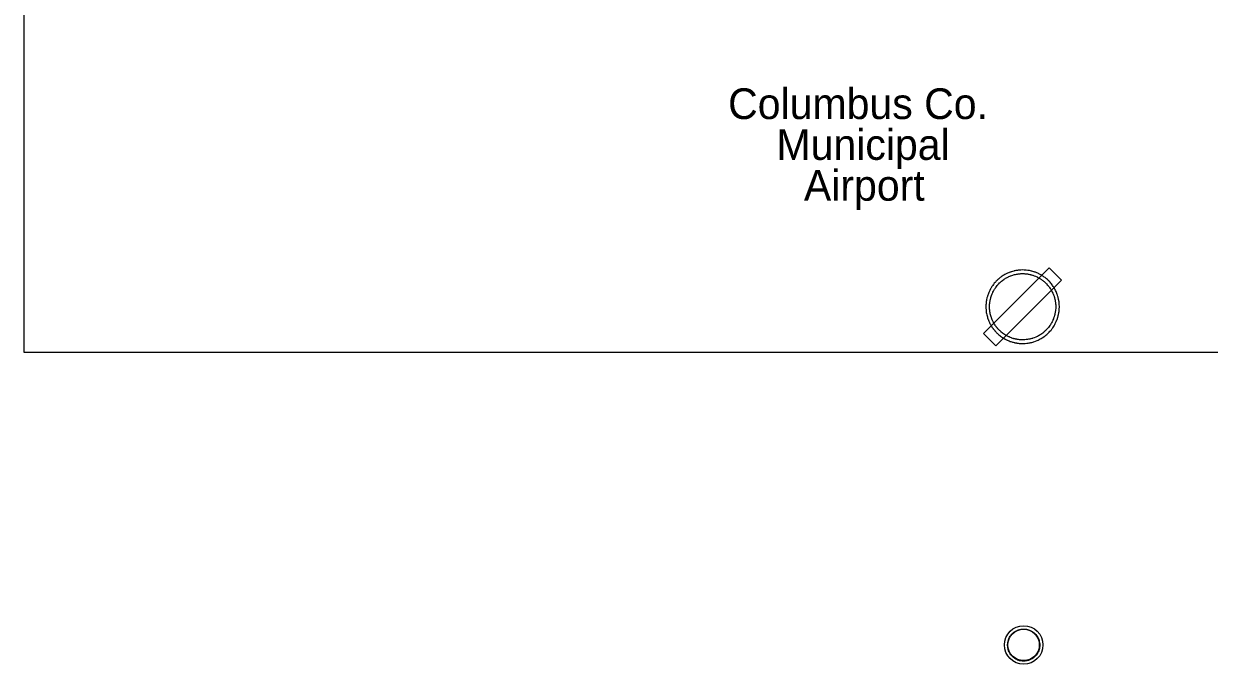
# Model space of a CAD drawing. Extents: x 5197761 to 5514561, y 1890130 to 2080942.
# Drawn here: x 5298905 to 5322096, y 1984861 to 1997380 of the extents above; entities that cross this region are included whole.
import ezdxf

# ---------------------------------------------------------------- set-up
doc = ezdxf.new("R2010")
doc.units = 0
for name, color, linetype in [('Exist Aviation Commercial or Municipal Label', 7, 'Continuous'), ('Exist Aviation Field Marked Auxiliary CELL', 7, 'Continuous'), ('Exist Civil Demographics Community CELL', 7, 'Continuous'), ('Map Preparation Inset Cut Line', 7, 'Continuous')]:
    doc.layers.add(name, color=color, linetype=linetype)

msp = doc.modelspace()

# ---------------------------------------------------------------- linework, layer by layer
at = {"layer": 'Exist Aviation Field Marked Auxiliary CELL'}
for points in [[(5319207, 1992370), (5318966, 1992611), (5317682, 1991327), (5317923, 1991086)], [(5318102, 1991216), (5318129, 1991203), (5318143, 1991196), (5318150, 1991193), (5318174, 1991183), (5318177, 1991181), (5318183, 1991179), (5318201, 1991172), (5318211, 1991169), (5318230, 1991163), (5318246, 1991158), (5318256, 1991155), (5318280, 1991149), (5318285, 1991148), (5318295, 1991146), (5318310, 1991143), (5318315, 1991142), (5318323, 1991140), (5318332, 1991139), (5318354, 1991135), (5318374, 1991133), (5318399, 1991131), (5318422, 1991130), (5318435, 1991130), (5318450, 1991130), (5318471, 1991130), (5318495, 1991131), (5318524, 1991134), (5318550, 1991137), (5318572, 1991142), (5318583, 1991143), (5318587, 1991144), (5318593, 1991146), (5318602, 1991148), (5318614, 1991150), (5318623, 1991152), (5318641, 1991157), (5318658, 1991162), (5318665, 1991165), (5318698, 1991176), (5318728, 1991188), (5318746, 1991196), (5318767, 1991206), (5318789, 1991218), (5318805, 1991226), (5318824, 1991238), (5318842, 1991250), (5318863, 1991265), (5318882, 1991279), (5318890, 1991285), (5318894, 1991288), (5318901, 1991294), (5318915, 1991305), (5318936, 1991324), (5318952, 1991340), (5318965, 1991353), (5318979, 1991368), (5318993, 1991385), (5319006, 1991400), (5319022, 1991421), (5319034, 1991438), (5319047, 1991458), (5319059, 1991477), (5319065, 1991486), (5319074, 1991503), (5319083, 1991520), (5319090, 1991533), (5319097, 1991547), (5319103, 1991562), (5319115, 1991590), (5319118, 1991600), (5319125, 1991618), (5319129, 1991631), (5319131, 1991639), (5319135, 1991650), (5319138, 1991662), (5319142, 1991679), (5319146, 1991695), (5319153, 1991731), (5319154, 1991737), (5319156, 1991756), (5319159, 1991772), (5319160, 1991784), (5319162, 1991810), (5319163, 1991841), (5319163, 1991861), (5319162, 1991888), (5319160, 1991912), (5319159, 1991923), (5319158, 1991933), (5319156, 1991945), (5319154, 1991962), (5319152, 1991970), (5319148, 1991991), (5319147, 1991997), (5319145, 1992005), (5319142, 1992019), (5319138, 1992035), (5319133, 1992051), (5319127, 1992072), (5319126, 1992076), (5319121, 1992090), (5319114, 1992108), (5319106, 1992127), (5319098, 1992147), (5319089, 1992164), (5319079, 1992185), (5319070, 1992201), (5319065, 1992210), (5319061, 1992216), (5319053, 1992229), (5319043, 1992245), (5319031, 1992263), (5319019, 1992279), (5319006, 1992297), (5318995, 1992309), (5318980, 1992327), (5318967, 1992342), (5318953, 1992356), (5318949, 1992359), (5318941, 1992367), (5318930, 1992378), (5318914, 1992393), (5318898, 1992405), (5318882, 1992418), (5318868, 1992428), (5318862, 1992433), (5318859, 1992435), (5318852, 1992439), (5318841, 1992447), (5318829, 1992455), (5318818, 1992462), (5318802, 1992471), (5318774, 1992486), (5318761, 1992493), (5318757, 1992495), (5318740, 1992503), (5318721, 1992512), (5318694, 1992522), (5318683, 1992526), (5318668, 1992531), (5318661, 1992533), (5318641, 1992540), (5318622, 1992544), (5318615, 1992546), (5318598, 1992550), (5318580, 1992554), (5318561, 1992557), (5318548, 1992559), (5318516, 1992563), (5318510, 1992564), (5318494, 1992565), (5318476, 1992566), (5318472, 1992566), (5318433, 1992567), (5318408, 1992566), (5318393, 1992565), (5318361, 1992562), (5318358, 1992562), (5318346, 1992560), (5318332, 1992558), (5318322, 1992556), (5318314, 1992555), (5318292, 1992550), (5318281, 1992548), (5318270, 1992545), (5318249, 1992540), (5318229, 1992533), (5318214, 1992529), (5318210, 1992527), (5318184, 1992518), (5318175, 1992514), (5318169, 1992512), (5318148, 1992503), (5318134, 1992496), (5318109, 1992485), (5318095, 1992476), (5318076, 1992465), (5318061, 1992456), (5318046, 1992446), (5318034, 1992438), (5318017, 1992426), (5318007, 1992419), (5317985, 1992401), (5317981, 1992397), (5317969, 1992387), (5317958, 1992377), (5317955, 1992374), (5317944, 1992364), (5317928, 1992348), (5317917, 1992336), (5317905, 1992324), (5317890, 1992306), (5317873, 1992284), (5317860, 1992266), (5317856, 1992261), (5317853, 1992257), (5317847, 1992248), (5317845, 1992244), (5317835, 1992230), (5317820, 1992204), (5317819, 1992201), (5317815, 1992195), (5317811, 1992187), (5317800, 1992166), (5317795, 1992155), (5317781, 1992125), (5317768, 1992090), (5317761, 1992072), (5317755, 1992053), (5317754, 1992047), (5317751, 1992037), (5317747, 1992020), (5317746, 1992016), (5317740, 1991990), (5317738, 1991979), (5317736, 1991971), (5317733, 1991952), (5317732, 1991946), (5317732, 1991940), (5317730, 1991925), (5317728, 1991907), (5317728, 1991899), (5317727, 1991892), (5317726, 1991873), (5317726, 1991865), (5317726, 1991849), (5317726, 1991835), (5317726, 1991815), (5317728, 1991798), (5317728, 1991792), (5317729, 1991776), (5317732, 1991756), (5317733, 1991746), (5317734, 1991738), (5317738, 1991716), (5317743, 1991693), (5317748, 1991671), (5317754, 1991648), (5317759, 1991632), (5317766, 1991612), (5317768, 1991606), (5317774, 1991589), (5317784, 1991564), (5317796, 1991538), (5317806, 1991518), (5317810, 1991510), (5317814, 1991503), (5317822, 1991489), (5317824, 1991485), (5317834, 1991468), (5317845, 1991452), (5317855, 1991437), (5317857, 1991434), (5317868, 1991420), (5317871, 1991415), (5317877, 1991407), (5317881, 1991402), (5317886, 1991396), (5317892, 1991389), (5317898, 1991382), (5317901, 1991378), (5317908, 1991370), (5317920, 1991357), (5317925, 1991351), (5317936, 1991340), (5317946, 1991331), (5317953, 1991324), (5317961, 1991317), (5317975, 1991304), (5317981, 1991299), (5317999, 1991285), (5318008, 1991278), (5318012, 1991274), (5318031, 1991260), (5318049, 1991249), (5318074, 1991233)], [(5318135, 1991279), (5318111, 1991294), (5318088, 1991308), (5318072, 1991319), (5318055, 1991331), (5318051, 1991334), (5318043, 1991340), (5318027, 1991353), (5318022, 1991358), (5318009, 1991369), (5318002, 1991376), (5317995, 1991382), (5317987, 1991391), (5317977, 1991401), (5317972, 1991406), (5317961, 1991417), (5317955, 1991425), (5317952, 1991428), (5317947, 1991434), (5317941, 1991441), (5317937, 1991446), (5317933, 1991451), (5317928, 1991458), (5317925, 1991462), (5317915, 1991475), (5317913, 1991478), (5317905, 1991491), (5317895, 1991506), (5317886, 1991521), (5317884, 1991525), (5317877, 1991537), (5317873, 1991544), (5317870, 1991551), (5317860, 1991569), (5317850, 1991592), (5317841, 1991615), (5317835, 1991630), (5317833, 1991635), (5317827, 1991653), (5317822, 1991668), (5317817, 1991688), (5317812, 1991708), (5317808, 1991729), (5317805, 1991749), (5317804, 1991756), (5317802, 1991765), (5317800, 1991783), (5317799, 1991798), (5317799, 1991803), (5317798, 1991818), (5317797, 1991837), (5317797, 1991849), (5317797, 1991863), (5317797, 1991871), (5317798, 1991888), (5317799, 1991894), (5317799, 1991901), (5317801, 1991918), (5317802, 1991931), (5317803, 1991936), (5317804, 1991942), (5317807, 1991958), (5317808, 1991966), (5317810, 1991976), (5317815, 1991999), (5317816, 1992003), (5317820, 1992018), (5317822, 1992027), (5317824, 1992032), (5317829, 1992050), (5317835, 1992066), (5317847, 1992098), (5317859, 1992125), (5317863, 1992134), (5317874, 1992154), (5317877, 1992160), (5317881, 1992166), (5317882, 1992168), (5317896, 1992192), (5317904, 1992205), (5317907, 1992208), (5317912, 1992216), (5317915, 1992220), (5317918, 1992224), (5317930, 1992241), (5317945, 1992261), (5317959, 1992277), (5317969, 1992288), (5317979, 1992299), (5317994, 1992313), (5318003, 1992322), (5318006, 1992324), (5318016, 1992334), (5318027, 1992343), (5318030, 1992346), (5318051, 1992362), (5318059, 1992369), (5318074, 1992380), (5318085, 1992387), (5318099, 1992396), (5318112, 1992404), (5318130, 1992414), (5318142, 1992422), (5318165, 1992432), (5318177, 1992438), (5318197, 1992446), (5318201, 1992448), (5318210, 1992452), (5318233, 1992460), (5318236, 1992461), (5318250, 1992466), (5318268, 1992471), (5318287, 1992476), (5318297, 1992479), (5318307, 1992481), (5318327, 1992485), (5318334, 1992486), (5318343, 1992487), (5318355, 1992489), (5318367, 1992491), (5318369, 1992491), (5318398, 1992494), (5318412, 1992495), (5318434, 1992496), (5318470, 1992495), (5318473, 1992495), (5318489, 1992494), (5318504, 1992493), (5318509, 1992492), (5318538, 1992489), (5318550, 1992487), (5318566, 1992484), (5318583, 1992480), (5318598, 1992477), (5318604, 1992475), (5318621, 1992471), (5318639, 1992465), (5318646, 1992463), (5318659, 1992459), (5318670, 1992455), (5318693, 1992446), (5318711, 1992438), (5318726, 1992431), (5318730, 1992429), (5318742, 1992423), (5318766, 1992410), (5318781, 1992401), (5318791, 1992395), (5318801, 1992388), (5318812, 1992381), (5318817, 1992377), (5318821, 1992375), (5318826, 1992371), (5318839, 1992361), (5318853, 1992350), (5318867, 1992339), (5318882, 1992325), (5318892, 1992315), (5318899, 1992309), (5318902, 1992305), (5318915, 1992293), (5318927, 1992279), (5318941, 1992264), (5318950, 1992253), (5318962, 1992236), (5318973, 1992222), (5318984, 1992206), (5318993, 1992191), (5319000, 1992179), (5319003, 1992174), (5319008, 1992166), (5319016, 1992152), (5319025, 1992133), (5319033, 1992117), (5319041, 1992099), (5319048, 1992082), (5319054, 1992066), (5319058, 1992054), (5319059, 1992050), (5319065, 1992031), (5319069, 1992016), (5319073, 1992002), (5319076, 1991990), (5319078, 1991982), (5319078, 1991977), (5319082, 1991958), (5319083, 1991951), (5319085, 1991935), (5319087, 1991924), (5319088, 1991916), (5319089, 1991906), (5319091, 1991884), (5319092, 1991860), (5319091, 1991842), (5319091, 1991814), (5319089, 1991791), (5319088, 1991780), (5319086, 1991765), (5319084, 1991748), (5319083, 1991742), (5319077, 1991710), (5319073, 1991696), (5319069, 1991680), (5319066, 1991670), (5319063, 1991660), (5319061, 1991653), (5319057, 1991640), (5319051, 1991624), (5319048, 1991615), (5319038, 1991590), (5319032, 1991577), (5319026, 1991564), (5319020, 1991553), (5319012, 1991537), (5319003, 1991522), (5318998, 1991514), (5318988, 1991496), (5318976, 1991479), (5318965, 1991463), (5318950, 1991445), (5318939, 1991431), (5318926, 1991416), (5318913, 1991402), (5318902, 1991390), (5318887, 1991376), (5318868, 1991359), (5318856, 1991349), (5318849, 1991343), (5318846, 1991341), (5318839, 1991335), (5318822, 1991322), (5318803, 1991309), (5318786, 1991299), (5318769, 1991288), (5318755, 1991280), (5318735, 1991270), (5318716, 1991261), (5318700, 1991253), (5318673, 1991243), (5318643, 1991232), (5318637, 1991230), (5318622, 1991226), (5318605, 1991221), (5318598, 1991220), (5318586, 1991217), (5318578, 1991215), (5318573, 1991214), (5318570, 1991213), (5318559, 1991212), (5318539, 1991208), (5318516, 1991205), (5318490, 1991202), (5318468, 1991201), (5318449, 1991201), (5318436, 1991201), (5318424, 1991201), (5318404, 1991202), (5318381, 1991204), (5318363, 1991206), (5318343, 1991209), (5318335, 1991210), (5318328, 1991212), (5318323, 1991213), (5318310, 1991215), (5318301, 1991217), (5318296, 1991218), (5318275, 1991224), (5318265, 1991226), (5318251, 1991231), (5318234, 1991236), (5318225, 1991239), (5318209, 1991245), (5318203, 1991247), (5318201, 1991249), (5318179, 1991258), (5318173, 1991261), (5318160, 1991267)]]:
    msp.add_lwpolyline(points, close=True, dxfattribs=at)
at = {"layer": 'Exist Civil Demographics Community CELL'}
msp.add_lwpolyline([(5318155, 1985288), (5318159, 1985310), (5318166, 1985336), (5318177, 1985365), (5318189, 1985388), (5318203, 1985411), (5318218, 1985432), (5318233, 1985449), (5318252, 1985467), (5318274, 1985486), (5318296, 1985500), (5318315, 1985512), (5318335, 1985522), (5318357, 1985531), (5318380, 1985538), (5318397, 1985543), (5318416, 1985546), (5318433, 1985549), (5318458, 1985550), (5318476, 1985549), (5318499, 1985548), (5318518, 1985545), (5318538, 1985541), (5318558, 1985536), (5318579, 1985528), (5318605, 1985516), (5318630, 1985502), (5318651, 1985488), (5318671, 1985472), (5318685, 1985460), (5318701, 1985442), (5318716, 1985423), (5318729, 1985405), (5318741, 1985385), (5318751, 1985364), (5318759, 1985344), (5318766, 1985324), (5318771, 1985306), (5318775, 1985281), (5318778, 1985263), (5318779, 1985239), (5318778, 1985216), (5318776, 1985193), (5318772, 1985171), (5318765, 1985146), (5318758, 1985123), (5318749, 1985103), (5318736, 1985079), (5318723, 1985057), (5318709, 1985039), (5318692, 1985020), (5318671, 1985000), (5318651, 1984983), (5318631, 1984969), (5318613, 1984959), (5318586, 1984947), (5318558, 1984936), (5318534, 1984930), (5318507, 1984925), (5318490, 1984923), (5318472, 1984922), (5318449, 1984922), (5318432, 1984923), (5318410, 1984926), (5318386, 1984931), (5318368, 1984937), (5318347, 1984944), (5318329, 1984952), (5318313, 1984961), (5318286, 1984977), (5318263, 1984995), (5318244, 1985012), (5318226, 1985032), (5318213, 1985048), (5318201, 1985064), (5318185, 1985093), (5318178, 1985107), (5318171, 1985123), (5318161, 1985156), (5318155, 1985184), (5318152, 1985205), (5318151, 1985230), (5318150, 1985249), (5318153, 1985275)], close=True, dxfattribs=at)
for centre, radius in [((5318465, 1985238), 377), ((5318464, 1985239), 307)]:
    msp.add_circle(centre, radius, dxfattribs=at)
at = {"layer": 'Map Preparation Inset Cut Line'}
msp.add_lwpolyline([(5337121, 2027499), (5337121, 2030497), (5298905, 2030497), (5298905, 1990962), (5337121, 1990962), (5337121, 1992535)], dxfattribs=at)

# ---------------------------------------------------------------- texts
at = {"layer": 'Exist Aviation Commercial or Municipal Label'}
for s, p in [('Columbus Co.', (5312683, 1995517)), ('Municipal', (5313628, 1994719)), (' Airport', (5313943, 1993921))]:
    msp.add_text(s, height=600, dxfattribs=at).set_placement(p)

doc.saveas('drawing.dxf')
